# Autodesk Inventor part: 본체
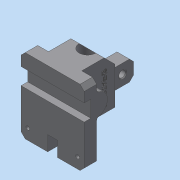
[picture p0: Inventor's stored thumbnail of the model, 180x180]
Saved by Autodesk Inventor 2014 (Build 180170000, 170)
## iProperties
Created: 2022-08
Part Number: 본체
Material: 일반
Document SubType Name: Modeling
Designer: dg
Density: 1 g/cm^3
Appearance: 기본값
Author: dg
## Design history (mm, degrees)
sketch "스케치1"
  geometry: L1 (0, 0)-(27, 0); L2 (27, 0)-(45, -18); L3 (45, -18)-(45, -58); L4 (45, -58)-(4, -58); L5 (4, -58)-(4, -90); L6 (4, -90)-(0, -90); L7 (0, -90)-(0, 0)
  constraints: 14 end point, 4 parallel, 1 horizontal, 1 perpendicular
  dimensions: "d0" = 45 distance between parallel lines of L3 L7; "d1" = 18 horizontal distance of L1.end L2.end; "d2" = 45 deg angle of L2 L3; "d3" = 32 distance of L4.end L5.end; "d4" = 4 distance of L5.end L6.end; "d5" = 90 distance of L6.end L1.start
extrude "돌출1" new body sketch "스케치1" stored distance "d6" = 40; taper "d7" = 0 deg
sketch "스케치2"
  geometry: L1 (0, -90)-(0, 0) reference; L2 (0, 0)-(-15, 0); L3 (-15, 0)-(-15, -17); L4 (-15, -17)-(-7, -17); L5 (-7, -17)-(-7, -37); L6 (-7, -37)-(-15, -37); L7 (-15, -37)-(-15, -90); L8 (-15, -90)-(0, -90); A1 r 13 centre (0, -27) between (0, -40) and (0, -14); 1 further point
  constraints: 14 end point, 4 parallel, 3 point on line, 2 perpendicular, 2 point on circle, 1 centre point, 1 collinear, 1 horizontal alignment, 1 midpoint
  dimensions: "d8" = 13 radius of A1; "d9" = 20 distance of L4.end L5.end; "d10" = 27 distance from line of L2 A1.centre; "d11" = 8 distance of L3.end L4.end; "d12" = 8 distance of L5.end L6.end; "d13" = 15 distance of L1.end L2.end
extrude "돌출2" join sketch "스케치2" stored distance "d14" = 76; taper "d15" = 0 deg
sketch "스케치3"
  geometry: L1 (58, -60)-(-18, -60) reference; 3 further points
  constraints: 1 midpoint, 1 vertical alignment
  dimensions: "d16" = 42 distance from line of L1 point (20, -18)
hole "구멍1" sketch "스케치3" at (20, -18) diameter "d17" = 20; stored, may be unused: countersink angle "d21" = 90 deg, drill point angle "d23" = 118 deg; dims "d18" = 6, "d19" = 29, "d20" = 7, "d22" = 8
sketch "스케치4"
  geometry: L1 (0, 0)-(40, 0) reference; C1 r 10 at (20, 23) reference; A1 r 29 centre (20, 23) between (2.336, 0) and (37.664, 0); 1 further point
  constraints: 2 point on circle, 2 point on line, 1 centre point, 1 coincident
  dimensions: "d24" = 58 diameter of A1
extrude "돌출3" cut sketch "스케치4" distance "d25" = 18; taper "d26" = 0 deg
sketch "스케치5"
  geometry: L1 (76, 0)-(0, 0) reference; L2 (55.664, 19)-(58, 19) reference; L3 (32, 13.627)-(32, 0); L4 (44, 13.627)-(44, 0); A1 r 29 centre (38, 42) between (20.336, 19) and (55.664, 19) reference; 1 further point
  constraints: 4 end point, 2 perpendicular, 2 point on circle, 2 point on line, 1 horizontal alignment
  dimensions: "d27" = 12 distance between parallel lines of L3 L4
extrude "돌출4" cut sketch "스케치5" distance "d28" = 18; taper "d29" = 0 deg
sketch "스케치6"
  geometry: L1 (0, 50)-(18, 50) reference; L2 (-58, 50)-(-40, 50) reference; L3 (10, 37)-(-50, 37); L4 (-10, -40)-(-30, -40) reference; 3 further points
  constraints: 2 end point, 2 midpoint, 1 vertical alignment
  dimensions: "d30" = 13 distance from line of L2 L3.end; "d31" = 13 distance from line of L1 L3.start; "d32" = 60 distance of L3.end L3.start
hole "구멍2" sketch "스케치6" at (10, 37), (-50, 37) diameter "d33" = 4.5; stored, may be unused: countersink angle "d37" = 90 deg, drill point angle "d39" = 118 deg; dims "d34" = 6, "d35" = 8, "d36" = 4.4, "d38" = 8
sketch "스케치7"
  geometry: L1 (45, -18)-(45, -58) reference; L2 (45, -29)-(75, -29); L3 (75, -29)-(75, -53); L4 (75, -53)-(45, -53); L5 (41.5, -58)-(12.5, -58) reference; L6 (-15, -90)-(-15, -37) reference; C1 r 4 at (62, -41); 2 further points
  constraints: 6 end point, 3 perpendicular, 2 point on line, 1 centre point, 1 horizontal alignment, 1 midpoint
  dimensions: "d40" = 5 distance from line of L1.end L4; "d41" = 24 distance of L2.end L3.end; "d42" = 30 distance of L2.start L2.end; "d43" = 8 diameter of C1; "d44" = 77 distance from line of L6 C1.centre
extrude "돌출5" join sketch "스케치7" stored distance "d45" = 15; taper "d46" = 0 deg
chamfer "모따기1" distance "d47" = 5; stored, may be unused: second distance "d48" = 2, angle "d49" = 45 deg
chamfer "모따기2" distance "d50" = 5; stored, may be unused: second distance "d51" = 2, angle "d52" = 45 deg
chamfer "모따기3" distance "d53" = 1; stored, may be unused: second distance "d54" = 2, angle "d55" = 45 deg
fillet "모깎기1" dims "d56" = 3
fillet "모깎기2" dims "d57" = 3
fillet "모깎기3" dims "d58" = 3
fillet "모깎기4" dims "d59" = 3
chamfer "모따기4" distance "d60" = 5; stored, may be unused: second distance "d61" = 2, angle "d62" = 45 deg
sketch "스케치8"
  geometry: L1 (58, 7)-(58, 40) reference; L2 (58, 45)-(18, 45) reference; 1 further point
  constraints: 1 other
  dimensions: "d63" = 26 distance from line of L1 point (32, 27); "d64" = 18 distance from line of L2 point (32, 27)
feature "엠보싱1" sketch "스케치8" dims "d0" = 45, "d1" = 18, "d2" = 45 deg, "d3" = 32, "d4" = 4, "d5" = 90, "d65" = 0.5, "d66" = 0
node "솔리드1"
